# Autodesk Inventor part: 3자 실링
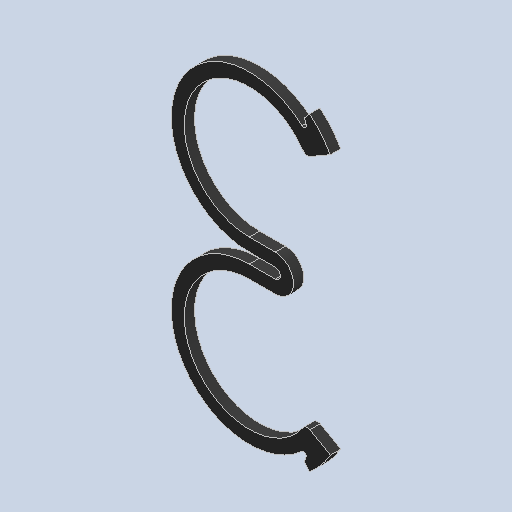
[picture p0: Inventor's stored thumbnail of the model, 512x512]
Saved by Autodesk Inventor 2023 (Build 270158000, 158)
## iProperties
Created: 2025-10
Part Number: 3자 실링
Material: 고무
Document SubType Name: Modeling
Designer: home
Density: 0.93 g/cm^3
Appearance: 기본값
Author: jhkim
Sending System: Autodesk Inventor 2026
Preprocessor: ST-DEVELOPER v20.1
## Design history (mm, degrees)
feature "솔리드1"
node "솔리드2"
